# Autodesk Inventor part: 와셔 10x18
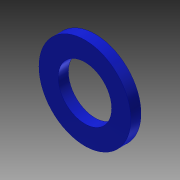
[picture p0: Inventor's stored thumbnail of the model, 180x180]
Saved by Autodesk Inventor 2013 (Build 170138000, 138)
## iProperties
Created: 2021-04
Part Number: 와셔 10x18
Material: 강철, 연강
Document SubType Name: Modeling
Designer: mdu-edu
Density: 7.86 g/cm^3
Author: mdu-edu
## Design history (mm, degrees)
sketch "스케치1"
  geometry: C1 r 5.25 at (0, 0); C2 r 9 at (0, 0); 1 further point
  constraints: 2 centre point, 2 coincident
  dimensions: "d0" = 10.5 diameter of C1; "d1" = 18 diameter of C2
extrude "돌출1" new body sketch "스케치1" distance "d2" = 2; taper "d3" = 0 deg
node "솔리드1"
